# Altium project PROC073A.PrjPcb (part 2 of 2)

## Sheet PROC073A_HD_Connector_60Pin.SchDoc
size 431 x 279 mm; Date: Not shown in title block; ApprovedBy: Not shown in title block; CheckedBy: Not shown in title block; Author: Not shown in title block; CompanyName: Not shown in title block; Engineer: Not shown in title block; Organization: Not shown in title block; Address1: Not shown in title block; Address2: Not shown in title block; Address3: Not shown in title block; Address4: Not shown in title block; DocumentNumber: 1; Revision: Use project parameter SCH_Rev; SheetNumber: 7; SheetTotal: 9; PageSetup: Record=PageOptions¦CenterHorizontal=True¦CenterVertical=True¦PrintScale=1.00¦XCorrection=1.00¦YCorrection=1.00¦PrintKind=0¦BorderSize=5000000¦LeftOffset=0¦BottomOffset=0¦Orientation=2¦PaperLength=1000¦PaperWidth=1000¦Scale=100¦PaperSource=15¦PrintQuality=600¦MediaType=1¦DitherType=10¦PaperKind=Letter¦PrintScaleMode=1
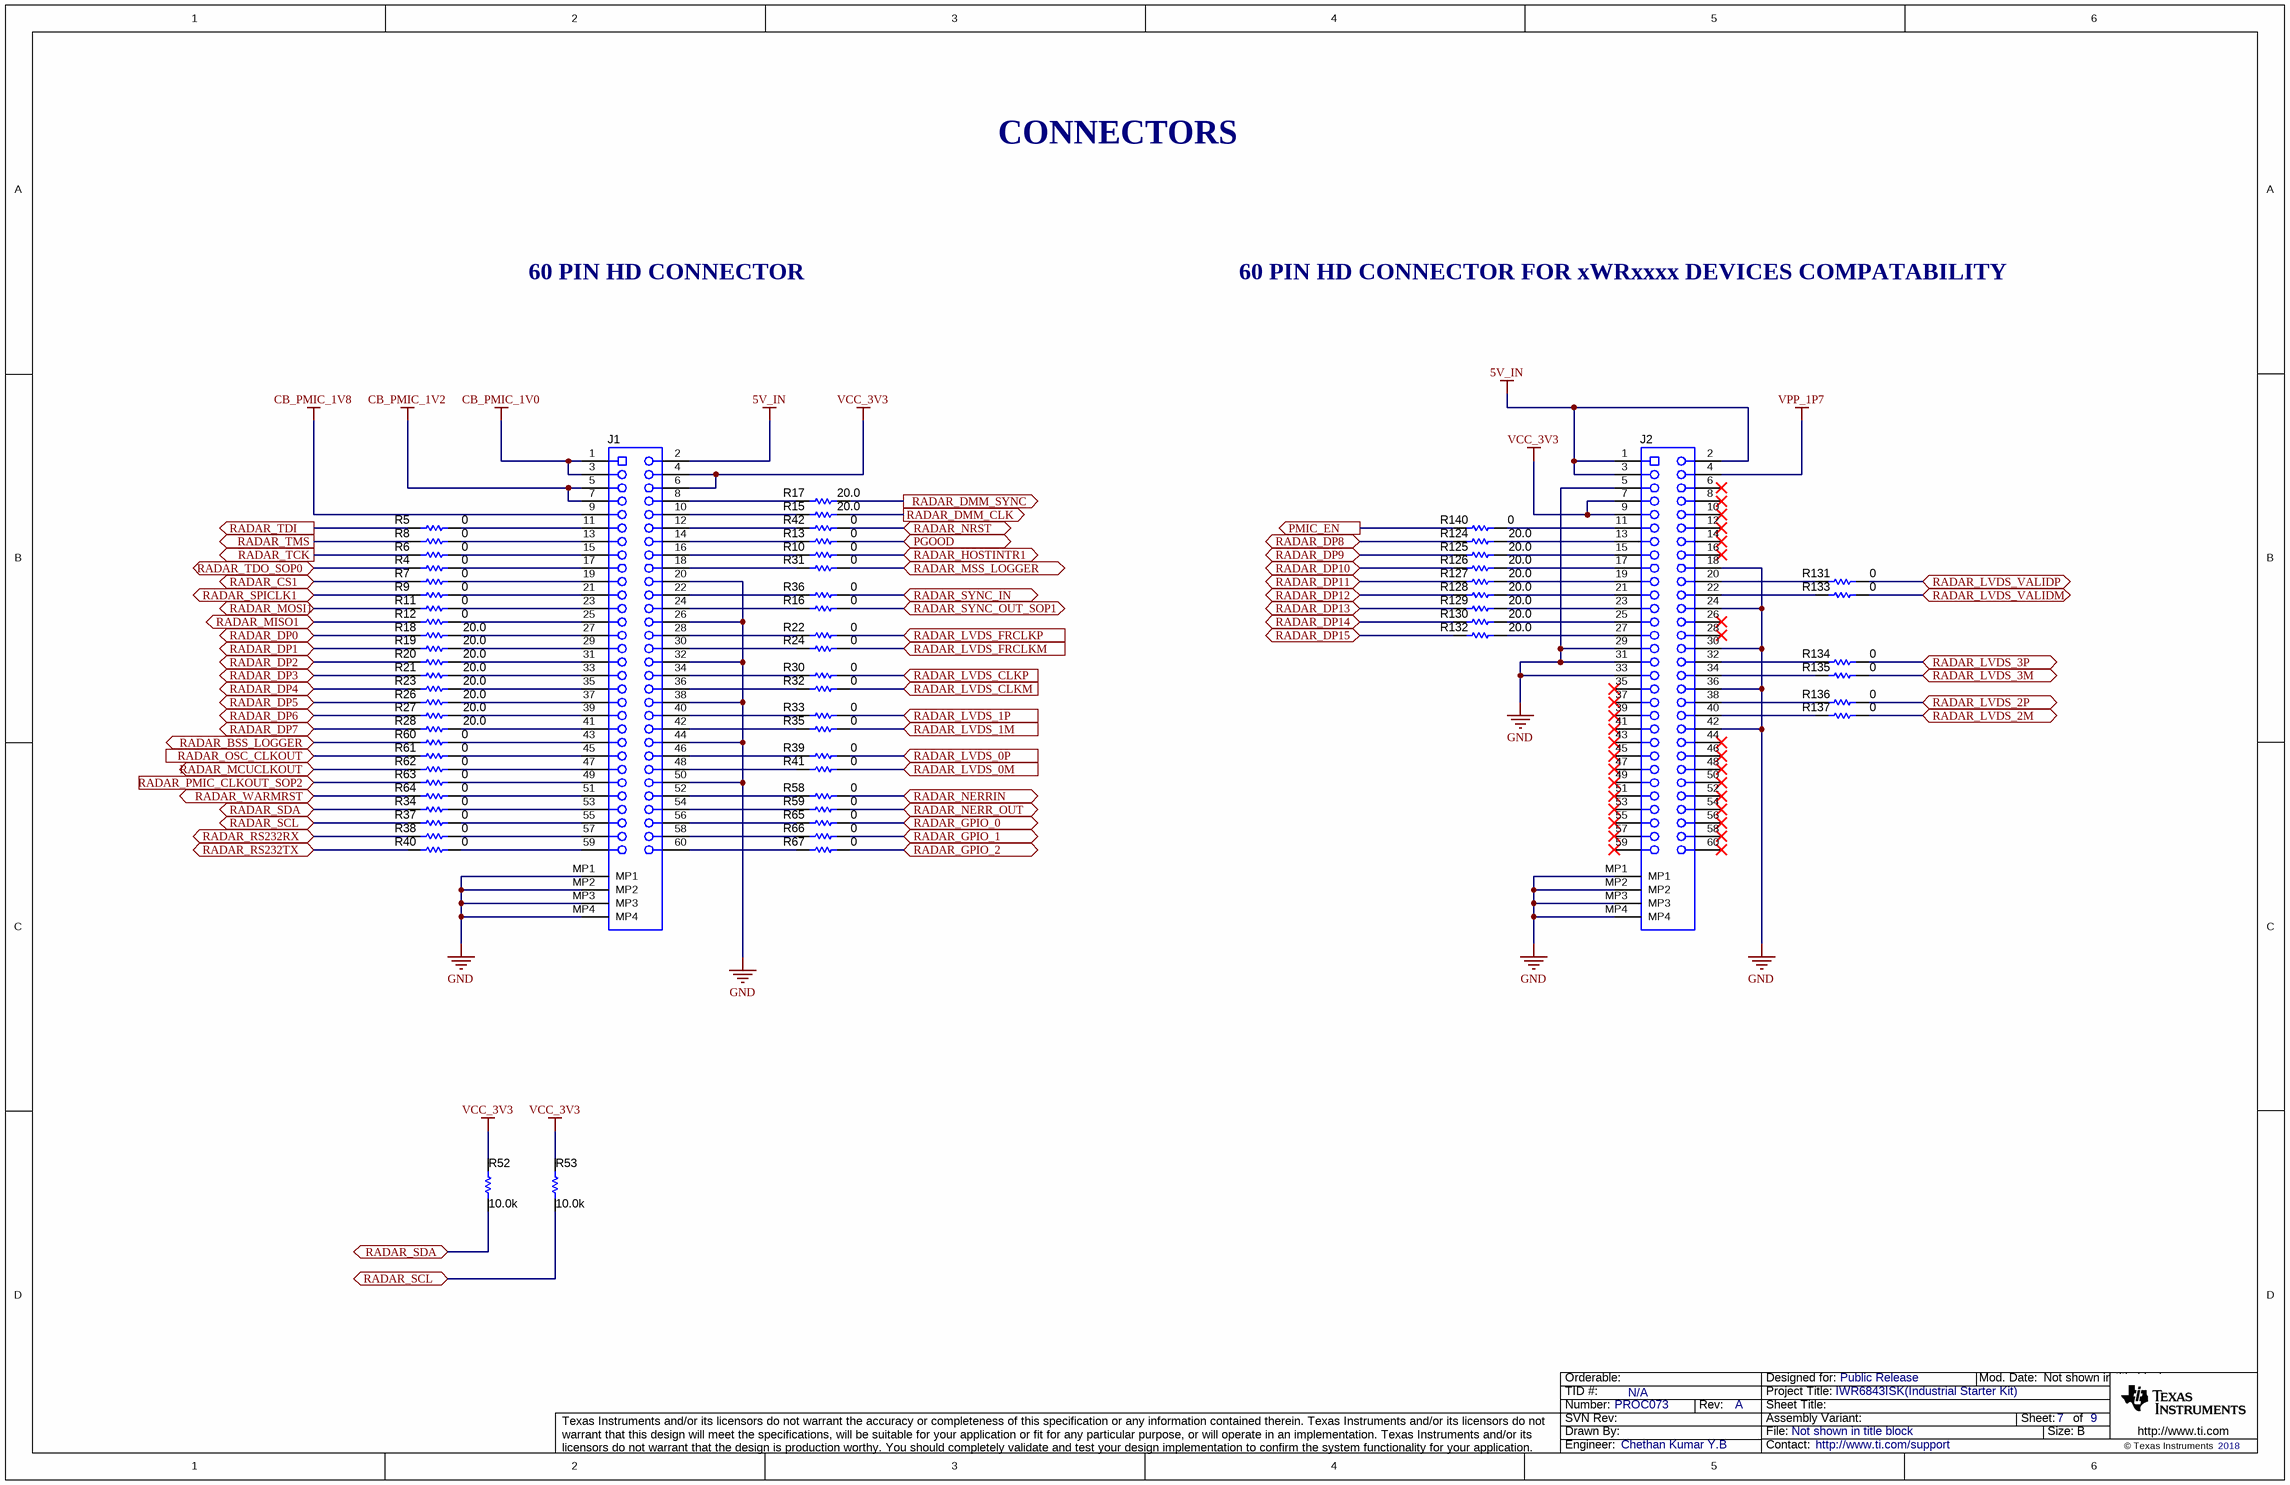
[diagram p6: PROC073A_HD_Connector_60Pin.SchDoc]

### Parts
J1  QSH-030-01-L-D-A  [Samtec_QSH-030-01-X-D-A]  (value not drawn)
J2  QSH-030-01-L-D-A  [Samtec_QSH-030-01-X-D-A]  (value not drawn)
R4  ValueDisplayed: 0  [0201_Silk]  (hidden comment: CRCW02010000Z0ED)
R5  ValueDisplayed: 0  [0201_Silk]  (hidden comment: CRCW02010000Z0ED)
R6  ValueDisplayed: 0  [0201_Silk]  (hidden comment: CRCW02010000Z0ED)
R7  ValueDisplayed: 0  [0201_Silk]  (hidden comment: CRCW02010000Z0ED)
R8  ValueDisplayed: 0  [0201_Silk]  (hidden comment: CRCW02010000Z0ED)
R9  ValueDisplayed: 0  [0201_Silk]  (hidden comment: CRCW02010000Z0ED)
R10  ValueDisplayed: 0  [0201_Silk]  (hidden comment: CRCW02010000Z0ED)
R11  ValueDisplayed: 0  [0201_Silk]  (hidden comment: CRCW02010000Z0ED)
R12  ValueDisplayed: 0  [0201_Silk]  (hidden comment: CRCW02010000Z0ED)
R13  ValueDisplayed: 0  [0201_Silk]  (hidden comment: CRCW02010000Z0ED)
R15  ValueDisplayed: 20.0  [0201_033]  (hidden comment: CRCW020120R0FNED)
R16  ValueDisplayed: 0  [0201_Silk]  (hidden comment: CRCW02010000Z0ED)
R17  ValueDisplayed: 20.0  [0201_033]  (hidden comment: CRCW020120R0FNED)
R18  ValueDisplayed: 20.0  [0201_033]  (hidden comment: CRCW020120R0FNED)
R19  ValueDisplayed: 20.0  [0201_033]  (hidden comment: CRCW020120R0FNED)
R20  ValueDisplayed: 20.0  [0201_033]  (hidden comment: CRCW020120R0FNED)
R21  ValueDisplayed: 20.0  [0201_033]  (hidden comment: CRCW020120R0FNED)
R22  ValueDisplayed: 0  [0201_Silk]  (hidden comment: CRCW02010000Z0ED)
R23  ValueDisplayed: 20.0  [0201_033]  (hidden comment: CRCW020120R0FNED)
R24  ValueDisplayed: 0  [0201_Silk]  (hidden comment: CRCW02010000Z0ED)
R26  ValueDisplayed: 20.0  [0201_033]  (hidden comment: CRCW020120R0FNED)
R27  ValueDisplayed: 20.0  [0201_033]  (hidden comment: CRCW020120R0FNED)
R28  ValueDisplayed: 20.0  [0201_033]  (hidden comment: CRCW020120R0FNED)
R30  ValueDisplayed: 0  [0201_Silk]  (hidden comment: CRCW02010000Z0ED)
R31  ValueDisplayed: 0  [0201_Silk]  (hidden comment: CRCW02010000Z0ED)
R32  ValueDisplayed: 0  [0201_Silk]  (hidden comment: CRCW02010000Z0ED)
R33  ValueDisplayed: 0  [0201_Silk]  (hidden comment: CRCW02010000Z0ED)
R34  ValueDisplayed: 0  [0201_Silk]  (hidden comment: CRCW02010000Z0ED)
R35  ValueDisplayed: 0  [0201_Silk]  (hidden comment: CRCW02010000Z0ED)
R36  ValueDisplayed: 0  [0201_Silk]  (hidden comment: CRCW02010000Z0ED)
R37  ValueDisplayed: 0  [0201_Silk]  (hidden comment: CRCW02010000Z0ED)
R38  ValueDisplayed: 0  [0201_Silk]  (hidden comment: CRCW02010000Z0ED)
R39  ValueDisplayed: 0  [0201_Silk]  (hidden comment: CRCW02010000Z0ED)
R40  ValueDisplayed: 0  [0201_Silk]  (hidden comment: CRCW02010000Z0ED)
R41  ValueDisplayed: 0  [0201_Silk]  (hidden comment: CRCW02010000Z0ED)
R42  ValueDisplayed: 0  [0201_Silk]  (hidden comment: CRCW02010000Z0ED)
R52  ValueDisplayed: 10.0k  [0402L]  (hidden comment: CRCW040210K0FKED)
R53  ValueDisplayed: 10.0k  [0402L]  (hidden comment: CRCW040210K0FKED)
R58  ValueDisplayed: 0  [0201_Silk]  (hidden comment: CRCW02010000Z0ED)
R59  ValueDisplayed: 0  [0201_Silk]  (hidden comment: CRCW02010000Z0ED)
R60  ValueDisplayed: 0  [0201_Silk]  (hidden comment: CRCW02010000Z0ED)
R61  ValueDisplayed: 0  [0201_Silk]  (hidden comment: CRCW02010000Z0ED)
R62  ValueDisplayed: 0  [0201_Silk]  (hidden comment: CRCW02010000Z0ED)
R63  ValueDisplayed: 0  [0201_Silk]  (hidden comment: CRCW02010000Z0ED)
R64  ValueDisplayed: 0  [0201_Silk]  (hidden comment: CRCW02010000Z0ED)
R65  ValueDisplayed: 0  [0201_Silk]  (hidden comment: CRCW02010000Z0ED)
R66  ValueDisplayed: 0  [0201_Silk]  (hidden comment: CRCW02010000Z0ED)
R67  ValueDisplayed: 0  [0201_Silk]  (hidden comment: CRCW02010000Z0ED)
R124  ValueDisplayed: 20.0  [0201_033]  (hidden comment: CRCW020120R0FNED)
R125  ValueDisplayed: 20.0  [0201_033]  (hidden comment: CRCW020120R0FNED)
R126  ValueDisplayed: 20.0  [0201_033]  (hidden comment: CRCW020120R0FNED)
R127  ValueDisplayed: 20.0  [0201_033]  (hidden comment: CRCW020120R0FNED)
R128  ValueDisplayed: 20.0  [0201_033]  (hidden comment: CRCW020120R0FNED)
R129  ValueDisplayed: 20.0  [0201_033]  (hidden comment: CRCW020120R0FNED)
R130  ValueDisplayed: 20.0  [0201_033]  (hidden comment: CRCW020120R0FNED)
R131  ValueDisplayed: 0  [0201_Silk]  (hidden comment: CRCW02010000Z0ED)
R132  ValueDisplayed: 20.0  [0201_033]  (hidden comment: CRCW020120R0FNED)
R133  ValueDisplayed: 0  [0201_Silk]  (hidden comment: CRCW02010000Z0ED)
R134  ValueDisplayed: 0  [0201_Silk]  (hidden comment: CRCW02010000Z0ED)
R135  ValueDisplayed: 0  [0201_Silk]  (hidden comment: CRCW02010000Z0ED)
R136  ValueDisplayed: 0  [0201_Silk]  (hidden comment: CRCW02010000Z0ED)
R137  ValueDisplayed: 0  [0201_Silk]  (hidden comment: CRCW02010000Z0ED)
R140  ValueDisplayed: 0  [0201_Silk]  (hidden comment: CRCW02010000Z0ED)

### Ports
PGOOD, PMIC_EN (out), RADAR_BSS_LOGGER, RADAR_CS1 (bidir), RADAR_DMM_CLK (out), RADAR_DMM_SYNC (out), RADAR_DP0 (bidir), RADAR_DP1 (bidir), RADAR_DP2 (bidir), RADAR_DP3 (bidir), RADAR_DP4 (bidir), RADAR_DP5 (bidir), RADAR_DP6 (bidir), RADAR_DP7 (bidir), RADAR_DP8, RADAR_DP9, RADAR_DP10, RADAR_DP11, RADAR_DP12, RADAR_DP13, RADAR_DP14, RADAR_DP15, RADAR_GPIO_0 (bidir), RADAR_GPIO_1 (bidir), RADAR_GPIO_2 (bidir), RADAR_HOSTINTR1, RADAR_LVDS_0M (in), RADAR_LVDS_0P (in), RADAR_LVDS_1M (in), RADAR_LVDS_1P (in), RADAR_LVDS_2M, RADAR_LVDS_2P, RADAR_LVDS_3M, RADAR_LVDS_3P, RADAR_LVDS_CLKM (in), RADAR_LVDS_CLKP (in), RADAR_LVDS_FRCLKM (in), RADAR_LVDS_FRCLKP (in), RADAR_LVDS_VALIDM, RADAR_LVDS_VALIDP, RADAR_MCUCLKOUT, RADAR_MISO1, RADAR_MOSI1, RADAR_MSS_LOGGER, RADAR_NERR_OUT, RADAR_NERRIN, RADAR_NRST, RADAR_OSC_CLKOUT (in), RADAR_PMIC_CLKOUT_SOP2 (in), RADAR_RS232RX, RADAR_RS232TX, RADAR_SCL, RADAR_SDA, RADAR_SPICLK1 (bidir), RADAR_SYNC_IN, RADAR_SYNC_OUT_SOP1, RADAR_TCK (out), RADAR_TDI (out), RADAR_TDO_SOP0, RADAR_TMS (out), RADAR_WARMRST

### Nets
5V_IN: J1.2 J2.1 J2.2 J2.3
CB_PMIC_1V0: J1.1 J1.3
CB_PMIC_1V2: J1.5 J1.7
CB_PMIC_1V8: J1.9
GND: J1.20 J1.26 J1.32 J1.38 J1.44 J1.50 J1.MP1 J1.MP2 J1.MP3 J1.MP4 J2.5 J2.18 J2.24 J2.29 J2.30 J2.31 J2.33 J2.36 J2.42 J2.MP1 J2.MP2 J2.MP3 J2.MP4
VCC_3V3: J1.4 J1.6 J2.7 J2.9 R52.2 R53.2
VPP_1P7: J2.4
PGOOD: R13.2 ; port PGOOD
PMIC_EN: R140.1 ; port PMIC_EN
RADAR_BSS_LOGGER: R60.2 ; port RADAR_BSS_LOGGER
RADAR_CS1: R7.1 ; port RADAR_CS1
RADAR_DMM_CLK: R15.1 ; port RADAR_DMM_CLK
RADAR_DMM_SYNC: R17.1 ; port RADAR_DMM_SYNC
RADAR_DP0: R18.1 ; port RADAR_DP0
RADAR_DP1: R19.1 ; port RADAR_DP1
RADAR_DP2: R20.1 ; port RADAR_DP2
RADAR_DP3: R21.1 ; port RADAR_DP3
RADAR_DP4: R23.1 ; port RADAR_DP4
RADAR_DP5: R26.1 ; port RADAR_DP5
RADAR_DP6: R27.1 ; port RADAR_DP6
RADAR_DP7: R28.1 ; port RADAR_DP7
RADAR_DP8: R124.1 ; port RADAR_DP8
RADAR_DP9: R125.1 ; port RADAR_DP9
RADAR_DP10: R126.1 ; port RADAR_DP10
RADAR_DP11: R127.1 ; port RADAR_DP11
RADAR_DP12: R128.1 ; port RADAR_DP12
RADAR_DP13: R129.1 ; port RADAR_DP13
RADAR_DP14: R130.1 ; port RADAR_DP14
RADAR_DP15: R132.1 ; port RADAR_DP15
RADAR_GPIO_0: R65.1 ; port RADAR_GPIO_0
RADAR_GPIO_1: R66.2 ; port RADAR_GPIO_1
RADAR_GPIO_2: R67.2 ; port RADAR_GPIO_2
RADAR_HOSTINTR1: R10.2 ; port RADAR_HOSTINTR1
RADAR_LVDS_0M: R41.2 ; port RADAR_LVDS_0M
RADAR_LVDS_0P: R39.2 ; port RADAR_LVDS_0P
RADAR_LVDS_1M: R35.2 ; port RADAR_LVDS_1M
RADAR_LVDS_1P: R33.2 ; port RADAR_LVDS_1P
RADAR_LVDS_2M: R137.2 ; port RADAR_LVDS_2M
RADAR_LVDS_2P: R136.2 ; port RADAR_LVDS_2P
RADAR_LVDS_3M: R135.2 ; port RADAR_LVDS_3M
RADAR_LVDS_3P: R134.2 ; port RADAR_LVDS_3P
RADAR_LVDS_CLKM: R32.2 ; port RADAR_LVDS_CLKM
RADAR_LVDS_CLKP: R30.2 ; port RADAR_LVDS_CLKP
RADAR_LVDS_FRCLKM: R24.2 ; port RADAR_LVDS_FRCLKM
RADAR_LVDS_FRCLKP: R22.2 ; port RADAR_LVDS_FRCLKP
RADAR_LVDS_VALIDM: R133.2 ; port RADAR_LVDS_VALIDM
RADAR_LVDS_VALIDP: R131.2 ; port RADAR_LVDS_VALIDP
RADAR_MCUCLKOUT: R62.2 ; port RADAR_MCUCLKOUT
RADAR_MISO1: R12.2 ; port RADAR_MISO1
RADAR_MOSI1: R11.1 ; port RADAR_MOSI1
RADAR_MSS_LOGGER: R31.2 ; port RADAR_MSS_LOGGER
RADAR_NERR_OUT: R59.2 ; port RADAR_NERR_OUT
RADAR_NERRIN: R58.2 ; port RADAR_NERRIN
RADAR_NRST: R42.1 ; port RADAR_NRST
RADAR_OSC_CLKOUT: R61.2 ; port RADAR_OSC_CLKOUT
RADAR_PMIC_CLKOUT_SOP2: R63.2 ; port RADAR_PMIC_CLKOUT_SOP2
RADAR_RS232RX: R38.1 ; port RADAR_RS232RX
RADAR_RS232TX: R40.1 ; port RADAR_RS232TX
RADAR_SCL: R37.1 R53.1 ; port RADAR_SCL
RADAR_SDA: R34.1 R52.1 ; port RADAR_SDA
RADAR_SPICLK1: R9.1 ; port RADAR_SPICLK1
RADAR_SYNC_IN: R36.2 ; port RADAR_SYNC_IN
RADAR_SYNC_OUT_SOP1: R16.2 ; port RADAR_SYNC_OUT_SOP1
RADAR_TCK: R6.2 ; port RADAR_TCK
RADAR_TDI: R5.1 ; port RADAR_TDI
RADAR_TDO_SOP0: R4.2 ; port RADAR_TDO_SOP0
RADAR_TMS: R8.2 ; port RADAR_TMS
RADAR_WARMRST: R64.2 ; port RADAR_WARMRST
NetJ1_8: J1.8 R17.2
NetJ1_10: J1.10 R15.2
NetJ1_11: J1.11 R5.2
NetJ1_12: J1.12 R42.2
NetJ1_13: J1.13 R8.1
NetJ1_14: J1.14 R13.1
NetJ1_15: J1.15 R6.1
NetJ1_16: J1.16 R10.1
NetJ1_17: J1.17 R4.1
NetJ1_18: J1.18 R31.1
NetJ1_19: J1.19 R7.2
NetJ1_21: J1.21 R9.2
NetJ1_22: J1.22 R36.1
NetJ1_23: J1.23 R11.2
NetJ1_24: J1.24 R16.1
NetJ1_25: J1.25 R12.1
NetJ1_27: J1.27 R18.2
NetJ1_28: J1.28 R22.1
NetJ1_29: J1.29 R19.2
NetJ1_30: J1.30 R24.1
NetJ1_31: J1.31 R20.2
NetJ1_33: J1.33 R21.2
NetJ1_34: J1.34 R30.1
NetJ1_35: J1.35 R23.2
NetJ1_36: J1.36 R32.1
NetJ1_37: J1.37 R26.2
NetJ1_39: J1.39 R27.2
NetJ1_40: J1.40 R33.1
NetJ1_41: J1.41 R28.2
NetJ1_42: J1.42 R35.1
NetJ1_43: J1.43 R60.1
NetJ1_45: J1.45 R61.1
NetJ1_46: J1.46 R39.1
NetJ1_47: J1.47 R62.1
NetJ1_48: J1.48 R41.1
NetJ1_49: J1.49 R63.1
NetJ1_51: J1.51 R64.1
NetJ1_52: J1.52 R58.1
NetJ1_53: J1.53 R34.2
NetJ1_54: J1.54 R59.1
NetJ1_55: J1.55 R37.2
NetJ1_56: J1.56 R65.2
NetJ1_57: J1.57 R38.2
NetJ1_58: J1.58 R66.1
NetJ1_59: J1.59 R40.2
NetJ1_60: J1.60 R67.1
NetJ2_11: J2.11 R140.2
NetJ2_13: J2.13 R124.2
NetJ2_15: J2.15 R125.2
NetJ2_17: J2.17 R126.2
NetJ2_19: J2.19 R127.2
NetJ2_20: J2.20 R131.1
NetJ2_21: J2.21 R128.2
NetJ2_22: J2.22 R133.1
NetJ2_23: J2.23 R129.2
NetJ2_25: J2.25 R130.2
NetJ2_27: J2.27 R132.2
NetJ2_32: J2.32 R134.1
NetJ2_34: J2.34 R135.1
NetJ2_38: J2.38 R136.1
NetJ2_40: J2.40 R137.1

Not connected (* = marked no-connect by the designer): J2 6* 8* 10* 12* 14* 16* 26* 28* 35* 37* 39* 41* 43* 44* 45* 46* 47* 48* 49* 50* 51* 52* 53* 54* 55* 56* 57* 58* 59* 60*

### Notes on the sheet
- CONNECTORS
- 60 PIN HD CONNECTOR
- 60 PIN HD CONNECTOR FOR xWRxxxx DEVICES COMPATABILITY

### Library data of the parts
J1 J2 = CMP-0075524-1: Receptacle, 0.5 mm, 30x2, Gold, TH; Manufacturer: Samtec; Pitch_mm: 0.5; Gender: Female; Green_REACh: Passed; CT: False; Shrouded: N; RowSpacing_mm: 5.73; Green_Lifecycle: Active; Row_Count: 2
R4-R13 R16 R22 R24 R30-R37 R39 R41 R42 R58-R67 R131 R133-R137 R140 = CMP-0027008-3: RES, 0, 5%, 0.05 W, 0201; Manufacturer: Vishay-Dale; Power_W: 50mW; TempCo: ppm/C; Value_Code: 0000; U/M: EA; Value: 0; EIA_Code: E24; SizeX_mm: 0.6; SizeY_mm: 0.3; SizeZ_mm: 0.26; Value2: 0.05W; SizeArea_mm2: 0.18; AEC Qualified: N; AEC Category: Q200
R15 R17-R21 R23 R26-R28 R124-R130 R132 = CMP-0078192-1: RES, 20.0, 1%, 0.05 W, 0201; Manufacturer: Vishay-Dale; Value_Code: 20R0; SizeArea_mm2: 0.18; AEC Qualified: N; AEC Category: Q200; Res_ohm: 20; Value: 20.0; SizeZ_mm: 0.33; EIA_Code: E96; TempCo: 200 ppm/C; Power_W: 50mW; VDC_V: 30V; SizeY_mm: 0.3; Value2: 0.05W; U/M: EA; SizeX_mm: 0.6
R38 R40 = CMP-0027008-3: RES, 0, 5%, 0.05 W, 0201; Manufacturer: Vishay-Dale; Power_W: 50mW; TempCo: ppm/C; Value_Code: 0000; U/M: EA; Value: 0; EIA_Code: E24; SizeX_mm: 0.6; SizeY_mm: 0.3; SizeZ_mm: 0.26; Value2: 0.05W; SizeArea_mm2: 0.18; CompType: Resistor; AEC Qualified: N; AEC Category: Q200; INSTALATION: DNP
R52 R53 = CMP-0025958-2: RES, 10.0 k, 1%, 0.063 W, 0402; Manufacturer: Vishay-Dale; Power_W: 63mW; TempCo: 100 ppm/C; Value_Code: 10k0; U/M: EA; Value: 10.0k; EIA_Code: E96; Res_ohm: 10k; SizeX_mm: 1; SizeY_mm: 0.5; SizeZ_mm: 0.6; Value2: 0.063W; VDC_V: 50V; AEC Category: Q200

## Sheet PROC073A_Temp_Current_sensor.SchDoc
size 431 x 279 mm; Date: Not shown in title block; ApprovedBy: Not shown in title block; CheckedBy: Not shown in title block; Author: Not shown in title block; CompanyName: Not shown in title block; Engineer: Not shown in title block; Organization: Not shown in title block; Address1: Not shown in title block; Address2: Not shown in title block; Address3: Not shown in title block; Address4: Not shown in title block; DocumentNumber: 1; Revision: Use project parameter SCH_Rev; SheetNumber: 8; SheetTotal: 9; PageSetup: Record=PageOptions¦CenterHorizontal=True¦CenterVertical=True¦PrintScale=1.00¦XCorrection=1.00¦YCorrection=1.00¦PrintKind=0¦BorderSize=5000000¦LeftOffset=0¦BottomOffset=0¦Orientation=2¦PaperLength=1000¦PaperWidth=1000¦Scale=100¦PaperSource=15¦PrintQuality=600¦MediaType=1¦DitherType=10¦PaperKind=Letter¦PrintScaleMode=1
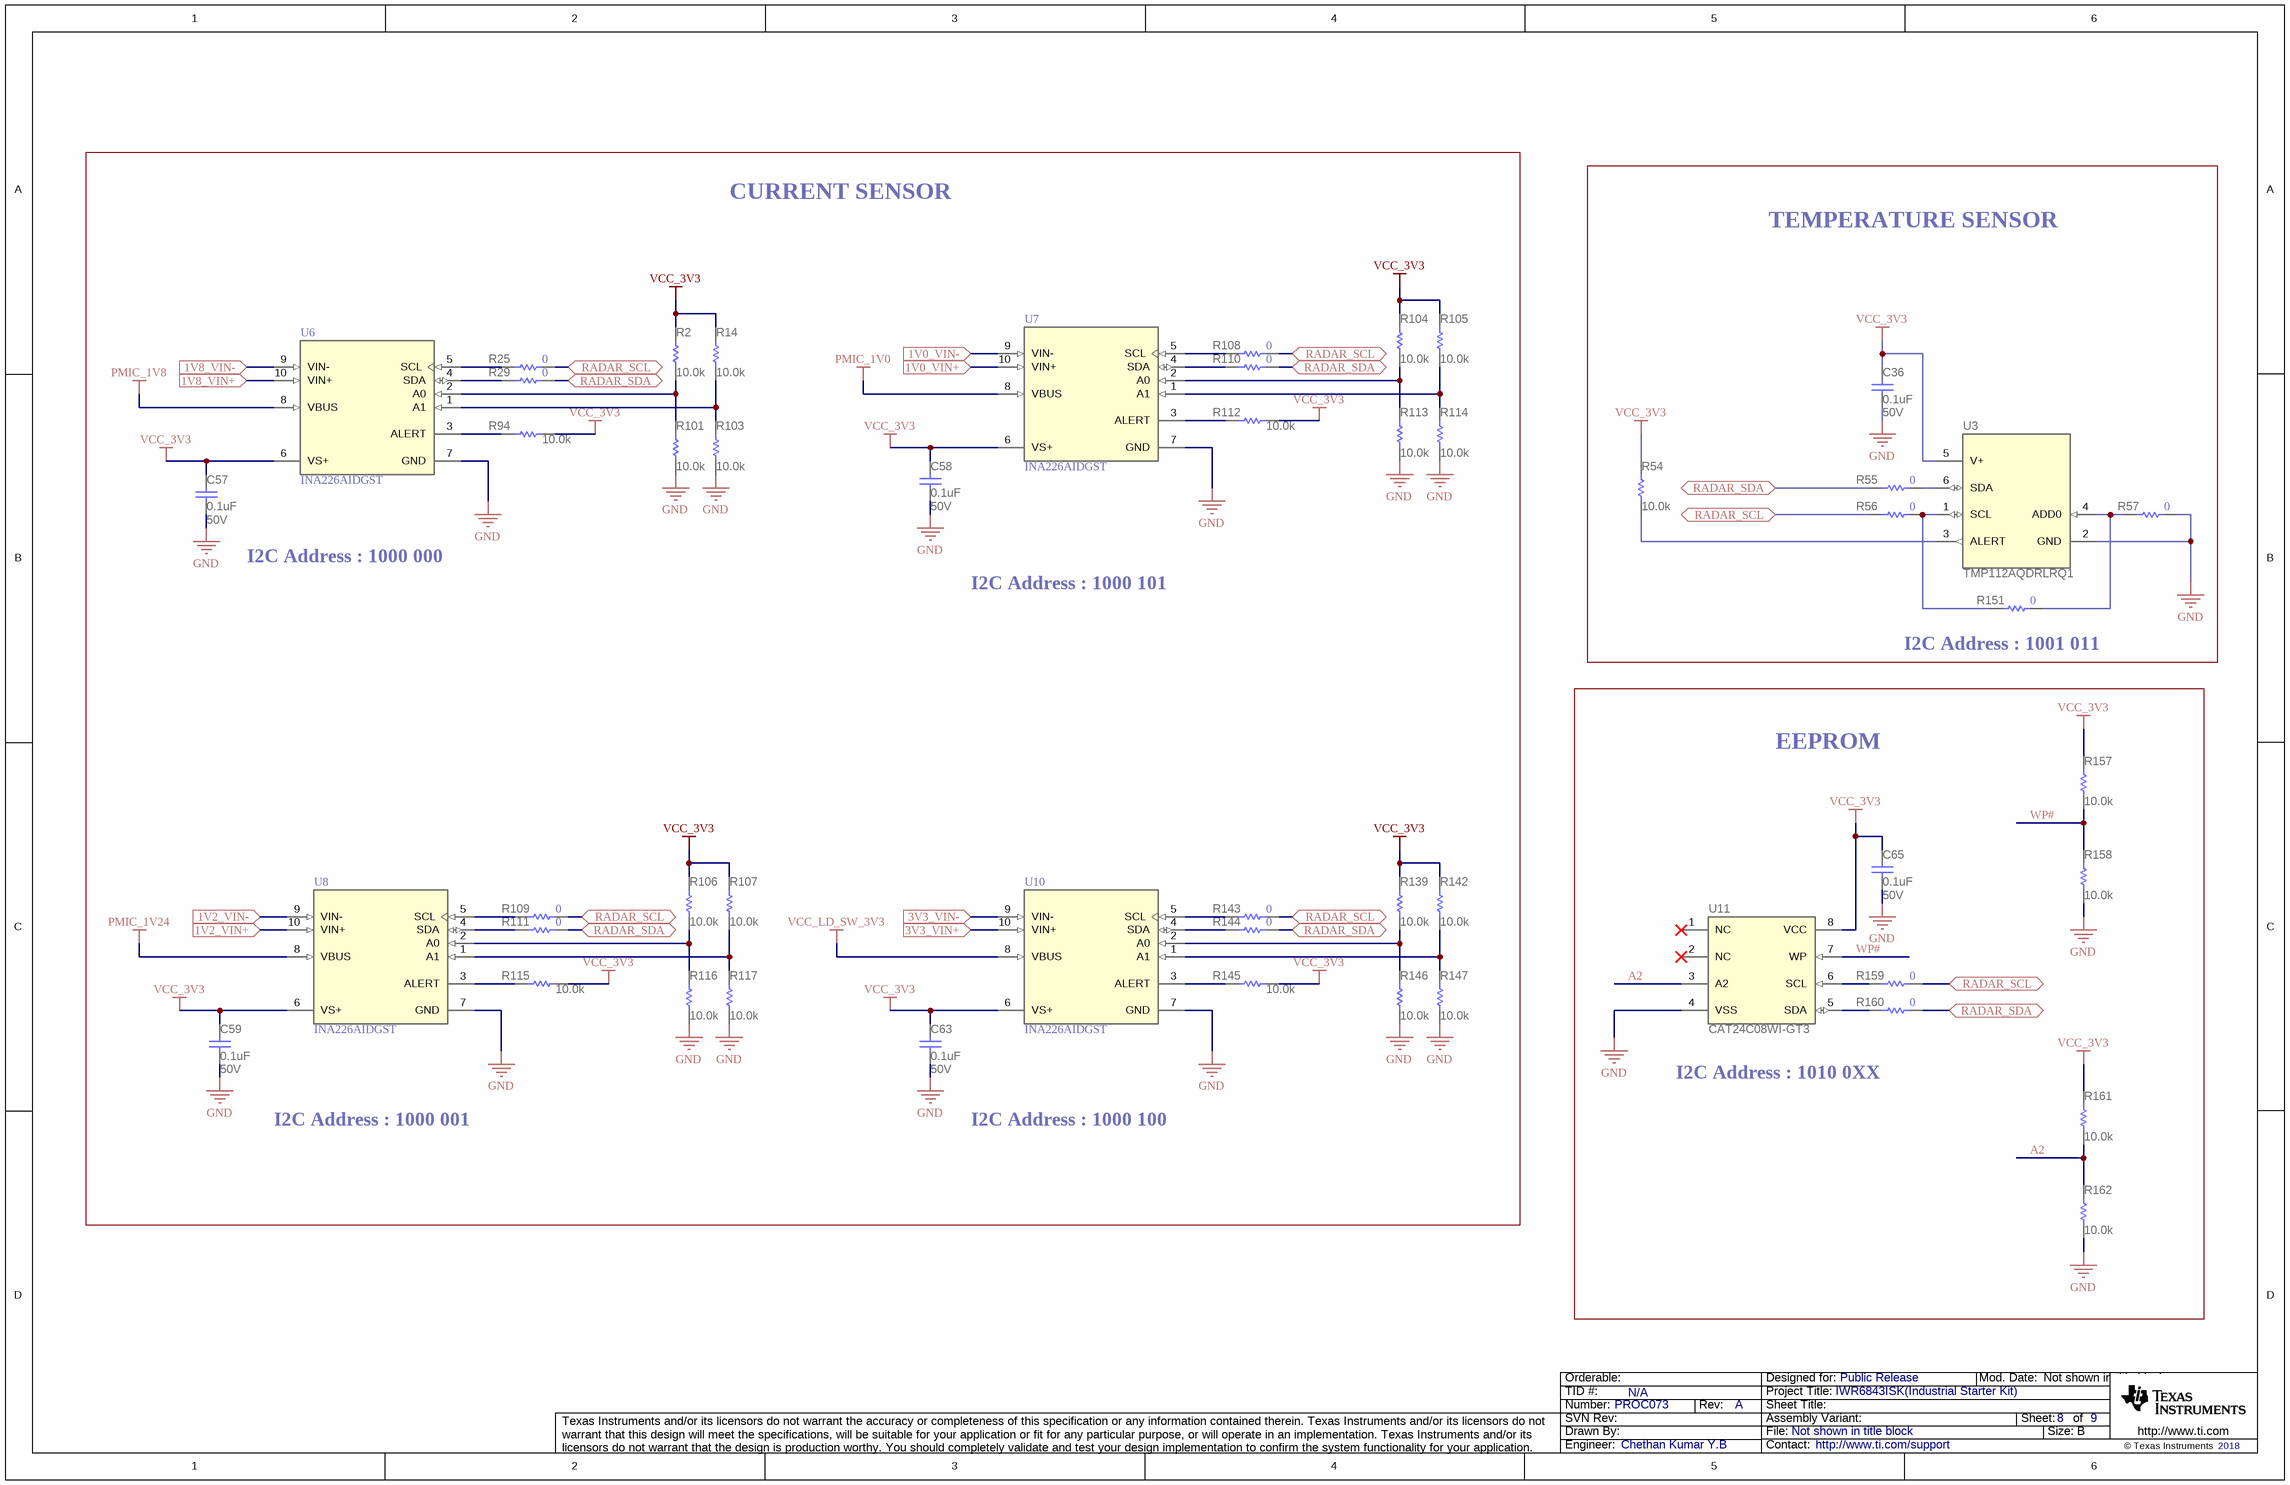
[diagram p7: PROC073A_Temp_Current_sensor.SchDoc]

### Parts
C36  VDC_V: 50V  ValueDisplayed: 0.1uF  [0402L]  (hidden comment: CGA2B3X7R1H104K050BB)
C57  VDC_V: 50V  ValueDisplayed: 0.1uF  [0402L]  (hidden comment: CGA2B3X7R1H104K050BB)
C58  VDC_V: 50V  ValueDisplayed: 0.1uF  [0402L]  (hidden comment: CGA2B3X7R1H104K050BB)
C59  VDC_V: 50V  ValueDisplayed: 0.1uF  [0402L]  (hidden comment: CGA2B3X7R1H104K050BB)
C63  VDC_V: 50V  ValueDisplayed: 0.1uF  [0402L]  (hidden comment: CGA2B3X7R1H104K050BB)
C65  VDC_V: 50V  ValueDisplayed: 0.1uF  [0402L]  (hidden comment: CGA2B3X7R1H104K050BB)
R2  ValueDisplayed: 10.0k  [0402L]  (hidden comment: CRCW040210K0FKED)
R14  ValueDisplayed: 10.0k  [0402L]  (hidden comment: CRCW040210K0FKED)
R25  ValueDisplayed: 0  [0201]  (hidden comment: CRCW02010000Z0ED)
R29  ValueDisplayed: 0  [0201]  (hidden comment: CRCW02010000Z0ED)
R54  ValueDisplayed: 10.0k  [0402L]  (hidden comment: CRCW040210K0FKED)
R55  ValueDisplayed: 0  [0201]  (hidden comment: CRCW02010000Z0ED)
R56  ValueDisplayed: 0  [0201]  (hidden comment: CRCW02010000Z0ED)
R57  Res_ohm: 0  [0402]  (hidden comment: CRCW04020000Z0ED)
R94  ValueDisplayed: 10.0k  [0402L]  (hidden comment: CRCW040210K0FKED)
R101  ValueDisplayed: 10.0k  [0402L]  (hidden comment: CRCW040210K0FKED)
R103  ValueDisplayed: 10.0k  [0402L]  (hidden comment: CRCW040210K0FKED)
R104  ValueDisplayed: 10.0k  [0402L]  (hidden comment: CRCW040210K0FKED)
R105  ValueDisplayed: 10.0k  [0402L]  (hidden comment: CRCW040210K0FKED)
R106  ValueDisplayed: 10.0k  [0402L]  (hidden comment: CRCW040210K0FKED)
R107  ValueDisplayed: 10.0k  [0402L]  (hidden comment: CRCW040210K0FKED)
R108  ValueDisplayed: 0  [0201]  (hidden comment: CRCW02010000Z0ED)
R109  ValueDisplayed: 0  [0201]  (hidden comment: CRCW02010000Z0ED)
R110  ValueDisplayed: 0  [0201]  (hidden comment: CRCW02010000Z0ED)
R111  ValueDisplayed: 0  [0201]  (hidden comment: CRCW02010000Z0ED)
R112  ValueDisplayed: 10.0k  [0402L]  (hidden comment: CRCW040210K0FKED)
R113  ValueDisplayed: 10.0k  [0402L]  (hidden comment: CRCW040210K0FKED)
R114  ValueDisplayed: 10.0k  [0402L]  (hidden comment: CRCW040210K0FKED)
R115  ValueDisplayed: 10.0k  [0402L]  (hidden comment: CRCW040210K0FKED)
R116  ValueDisplayed: 10.0k  [0402L]  (hidden comment: CRCW040210K0FKED)
R117  ValueDisplayed: 10.0k  [0402L]  (hidden comment: CRCW040210K0FKED)
R139  ValueDisplayed: 10.0k  [0402L]  (hidden comment: CRCW040210K0FKED)
R142  ValueDisplayed: 10.0k  [0402L]  (hidden comment: CRCW040210K0FKED)
R143  ValueDisplayed: 0  [0201]  (hidden comment: CRCW02010000Z0ED)
R144  ValueDisplayed: 0  [0201]  (hidden comment: CRCW02010000Z0ED)
R145  ValueDisplayed: 10.0k  [0402L]  (hidden comment: CRCW040210K0FKED)
R146  ValueDisplayed: 10.0k  [0402L]  (hidden comment: CRCW040210K0FKED)
R147  ValueDisplayed: 10.0k  [0402L]  (hidden comment: CRCW040210K0FKED)
R151  Res_ohm: 0  [0402]  (hidden comment: CRCW04020000Z0ED)
R157  ValueDisplayed: 10.0k  [0402L]  (hidden comment: CRCW040210K0FKED)
R158  ValueDisplayed: 10.0k  [0402L]  (hidden comment: CRCW040210K0FKED)
R159  ValueDisplayed: 0  [0201]  (hidden comment: CRCW02010000Z0ED)
R160  ValueDisplayed: 0  [0201]  (hidden comment: CRCW02010000Z0ED)
R161  ValueDisplayed: 10.0k  [0402L]  (hidden comment: CRCW040210K0FKED)
R162  ValueDisplayed: 10.0k  [0402L]  (hidden comment: CRCW040210K0FKED)
U3  TMP112AQDRLRQ1  [DRL0006A]
U6  INA226AIDGST  [DGS0010A_L]
U7  INA226AIDGST  [DGS0010A_L]
U8  INA226AIDGST  [DGS0010A_L]
U10  INA226AIDGST  [DGS0010A_L]
U11  CAT24C08WI-GT3  [SOIC-8]

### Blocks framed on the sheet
CURRENT SENSOR: C57-C59 C63 R2 R14 R25 R29 R94 R101 R103-R117 R139 R142-R147 U6-U8 U10
TEMPERATURE SENSOR: C36 R54-R57 R151 U3
EEPROM: C65 R157-R162 U11

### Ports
1V0_VIN+ (in), 1V0_VIN- (in), 1V2_VIN+ (in), 1V2_VIN- (in), 1V8_VIN+ (in), 1V8_VIN- (in), 3V3_VIN+ (in), 3V3_VIN- (in), RADAR_SCL, RADAR_SDA

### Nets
CB_PMIC_1V0: U7.9(VIN-) ; port 1V0_VIN-
CB_PMIC_1V2: U8.9(VIN-) ; port 1V2_VIN-
CB_PMIC_1V8: U6.9(VIN-) ; port 1V8_VIN-
GND: C36.1 C57.1 C58.1 C59.1 C63.1 C65.1 R57.2 R101.1 R103.1 R113.1 R114.1 R116.1 R117.1 R146.1 R147.1 R158.1 R162.1 U3.2(GND) U6.7(GND) U7.7(GND) U8.7(GND) U10.7(GND) U11.4(VSS)
PMIC_1V0: U7.8(VBUS) U7.10(VIN+) ; port 1V0_VIN+
PMIC_1V8: U6.8(VBUS) U6.10(VIN+) ; port 1V8_VIN+
PMIC_1V24: U8.8(VBUS) U8.10(VIN+) ; port 1V2_VIN+
RADAR_3V3: U10.9(VIN-) ; port 3V3_VIN-
VCC_3V3: C36.2 C57.2 C58.2 C59.2 C63.2 C65.2 R2.2 R14.2 R54.2 R94.1 R104.2 R105.2 R106.2 R107.2 R112.1 R115.1 R139.2 R142.2 R145.1 R157.2 R161.2 U3.5(V+) U6.6(VS+) U7.6(VS+) U8.6(VS+) U10.6(VS+) U11.8(VCC)
VCC_LD_SW_3V3: U10.8(VBUS) U10.10(VIN+) ; port 3V3_VIN+
A2: R161.1 R162.2 U11.3(A2)
RADAR_SCL: R25.2 R56.1 R108.2 R109.2 R143.2 R159.2 ; port RADAR_SCL
RADAR_SDA: R29.2 R55.1 R110.2 R111.2 R144.2 R160.2 ; port RADAR_SDA
WP#: R157.1 R158.2 U11.7(WP)
NetR2_1: R2.1 R101.2 U6.2(A0)
NetR14_1: R14.1 R103.2 U6.1(A1)
NetR25_1: R25.1 U6.5(SCL)
NetR29_1: R29.1 U6.4(SDA)
NetR54_1: R54.1 U3.3(ALERT)
NetR55_2: R55.2 U3.6(SDA)
NetR56_2: R56.2 R151.1 U3.1(SCL)
NetR57_1: R57.1 R151.2 U3.4(ADD0)
NetR94_2: R94.2 U6.3(ALERT)
NetR104_1: R104.1 R113.2 U7.2(A0)
NetR105_1: R105.1 R114.2 U7.1(A1)
NetR106_1: R106.1 R116.2 U8.2(A0)
NetR107_1: R107.1 R117.2 U8.1(A1)
NetR108_1: R108.1 U7.5(SCL)
NetR109_1: R109.1 U8.5(SCL)
NetR110_1: R110.1 U7.4(SDA)
NetR111_1: R111.1 U8.4(SDA)
NetR112_2: R112.2 U7.3(ALERT)
NetR115_2: R115.2 U8.3(ALERT)
NetR139_1: R139.1 R146.2 U10.2(A0)
NetR142_1: R142.1 R147.2 U10.1(A1)
NetR143_1: R143.1 U10.5(SCL)
NetR144_1: R144.1 U10.4(SDA)
NetR145_2: R145.2 U10.3(ALERT)
NetR159_1: R159.1 U11.6(SCL)
NetR160_1: R160.1 U11.5(SDA)

Not connected (* = marked no-connect by the designer): U11 1(NC)* 2(NC)*

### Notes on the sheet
- I2C Address : 1000 000
- I2C Address : 1000 101
- (near R151) I2C Address : 1001 011
- I2C Address : 1010 0XX
- I2C Address : 1000 001
- I2C Address : 1000 100

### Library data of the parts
C36 C57-C59 C63 C65 = CMP-0006325-2: CAP, CERM, 0.1 uF, 50 V, +/- 10%, X7R, AEC-Q200 Grade 1, 0402; Manufacturer: TDK; TaMin_C: -55°C; ESR_ohm: 0.039064; Polarized: N; SizeAreaWB_mm2: 3; Value1: 0.039064 ohm; U/M: EA; Value: 0.1uF; TaMax_C: 125°C; SizeZ_mm: 0.6; SizeX_mm: 1; SizeY_mm: 0.5; Cap_Case: 0402; AEC Qualified: Y; Cap_F: 100nF; IRMS_A: 8.14669dA; AEC Category: Q200
R2 R14 R107 R113 R114 R116 R139 R142 R146 R147 R157 R158 R161 R162 = CMP-0025958-2: RES, 10.0 k, 1%, 0.063 W, 0402; Manufacturer: Vishay-Dale; Power_W: 63mW; TempCo: 100 ppm/C; Value_Code: 10k0; U/M: EA; Value: 10.0k; EIA_Code: E96; Res_ohm: 10k; SizeX_mm: 1; SizeY_mm: 0.5; SizeZ_mm: 0.6; Value2: 0.063W; CompType: Resistor; VDC_V: 50V; AEC Category: Q200; INSTALLATION: DNP
R25 R29 R55 R56 R108-R111 R143 R144 R159 R160 = CMP-0027008-4: RES, 0, 5%, 0.05 W, 0201; Manufacturer: Vishay-Dale; Power_W: 50mW; TempCo: ppm/C; Value_Code: 0000; Value: 0; EIA_Code: E24; SizeX_mm: 0.6; SizeY_mm: 0.3; SizeZ_mm: 0.26; Value2: 0.05W; SizeArea_mm2: 0.18; AEC Qualified: N; AEC Category: Q200
R54 R94 R101 R103-R106 R112 R115 R117 R145 = CMP-0025958-2: as R52 on sheet PROC073A_HD_Connector_60Pin
R57 = CMP-0026822-3: RES, 0, 5%, 0.063 W, AEC-Q200 Grade 0, 0402; Manufacturer: Vishay-Dale; Power_W: 63mW; TempCo: 200 ppm/C; Value_Code: 0000; Value: 0; EIA_Code: E24; SizeX_mm: 1; SizeY_mm: 0.5; SizeZ_mm: 0.6; Value2: 0.063W; CompType: Resistor; AEC Qualified: Y; VDC_V: 50V; AEC Category: Q200; INSTALLATION: DNP
R151 = CMP-0026822-3: RES, 0, 5%, 0.063 W, AEC-Q200 Grade 0, 0402; Manufacturer: Vishay-Dale; Power_W: 63mW; TempCo: 200 ppm/C; Value_Code: 0000; Value: 0; EIA_Code: E24; SizeX_mm: 1; SizeY_mm: 0.5; SizeZ_mm: 0.6; Value2: 0.063W; CompType: Resistor; AEC Qualified: Y; VDC_V: 50V; AEC Category: Q200
U3 = CMP-0067398-2: Automotive Grade, 1.4V-Capable +/-0.5degC Temperature Sensor with Alert Function and I2C/SMBus, DRL0006A (SOT-OTHER-6); Manufacturer: Texas Instruments; SizeZ_mm: 0.6; SizeX_mm: 1.6; SizeArea_mm2: 2.56; CompType: IC; U/M: EA; SizeAreaWB_mm2: 6.76
U6-U8 U10 = CMP-0037978-1: High-Side Measurement, Bi-Directional Current / Power Monitor with I2C Interface, 2.7 to 5.5 V, -40 to 125 degC, 10-pin SOP (DGS10), Green (RoHS & no Sb/Br); Vs(Min)(V): 2.7; Rating: Catalog; Quiescent Current (+/-)(Typ)(mA): 0.33; Input Offset (+/-)(Max)(uV): 10; CMRR(Min)(dB): 126; Vs(Max)(V): 5.5; Common Mode Range(Max)(V): 36; Input Offset Drift (+/-)(Max)(uV/Degrees Celsius): 0.1; Common Mode Range(Min)(V): 0; SubFamily: Current Shunt Monitor; Gain(V/V): 1; Small-Signal Bandwidth(Typ)(MHz): 0.007
U11 = CMP-0005309-2: IC, EEPROM, 8KBIT, 400KHZ, 8SOIC; Manufacturer: ON Semiconductor; SizeAreaWB_mm2: 55.131; SizeZ_mm: 1.75; SizeX_mm: 5.99; SizeY_mm: 4.9; SizeArea_mm2: 29.351

## Sheet PROC073A_EVM_Hardware.SchDoc
size 431 x 279 mm; Date: Not shown in title block; ApprovedBy: Not shown in title block; CheckedBy: Not shown in title block; Author: Not shown in title block; CompanyName: Not shown in title block; Engineer: Not shown in title block; Organization: Not shown in title block; Address1: Not shown in title block; Address2: Not shown in title block; Address3: Not shown in title block; Address4: Not shown in title block; DocumentNumber: 1; Revision: Use project parameter SCH_Rev; SheetNumber: 9; SheetTotal: 9; PageSetup: Record=PageOptions¦CenterHorizontal=True¦CenterVertical=True¦PrintScale=1.00¦XCorrection=1.00¦YCorrection=1.00¦PrintKind=0¦BorderSize=5000000¦LeftOffset=0¦BottomOffset=0¦Orientation=2¦PaperLength=1000¦PaperWidth=1000¦Scale=100¦PaperSource=15¦PrintQuality=600¦MediaType=1¦DitherType=10¦PaperKind=Letter¦PrintScaleMode=1
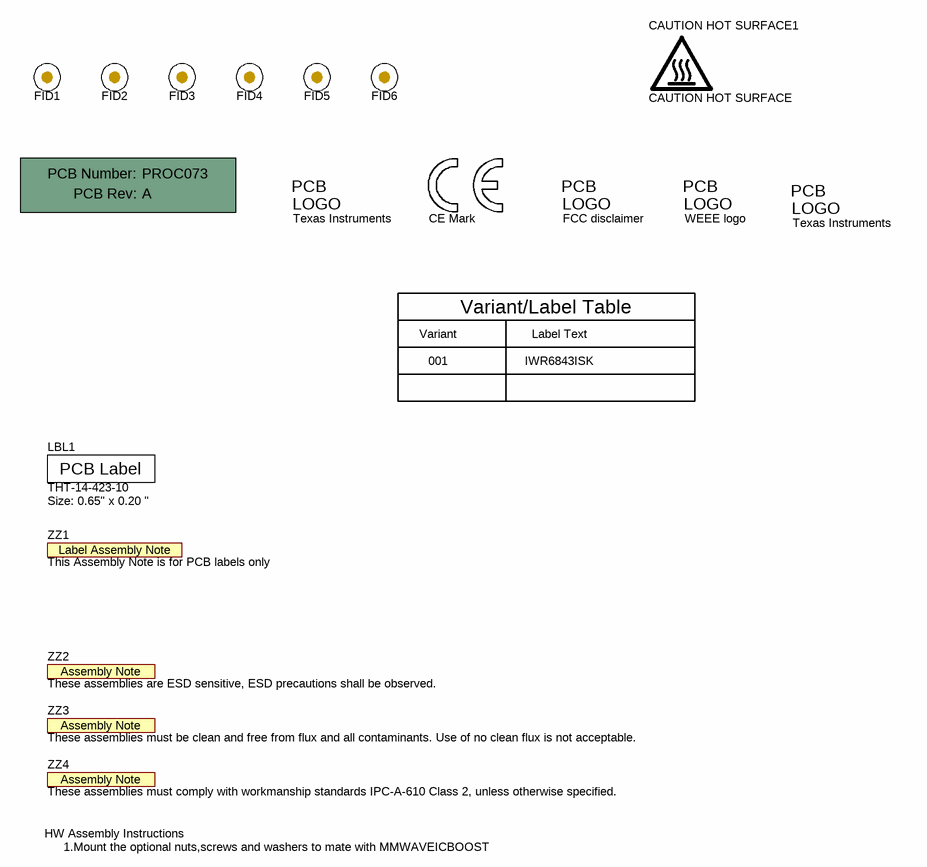
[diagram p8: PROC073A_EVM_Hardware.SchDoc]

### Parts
!PCB  Printed Circuit Board  (value not drawn)  (mechanical)
CAUTION_HOT_SURFACE1  CAUTION HOT SURFACE  [IEC_HotSurface_Small]  (no BOM)
FID1  Fiducial  [Fiducial10-20]  (value not drawn)
FID2  Fiducial  [Fiducial10-20]  (value not drawn)
FID3  Fiducial  [Fiducial10-20]  (value not drawn)
FID4  Fiducial  [Fiducial10-20]  (value not drawn)
FID5  Fiducial  [Fiducial10-20]  (value not drawn)
FID6  Fiducial  [Fiducial10-20]  (value not drawn)
LBL1  THT-14-423-10  Note: Size: 0.65" x 0.20 "  [Label_650x200]
Logo1  Texas Instruments  [TI_Stacked_Overlay_Small]  (no BOM)
Logo2  CE Mark  [CE_Mark_5mm]  (no BOM)
Logo3  FCC disclaimer  [FCC_disclaimer]  (no BOM)
Logo4  WEEE logo  [WEEE_Minimum]  (no BOM)
Logo5  Texas Instruments  [TI_Symbol_Overlay_Small]  (no BOM)
ZZ1  This Assembly Note is for PCB labels only  [AssemblyNoteLabel]  (no BOM)
ZZ2  These assemblies are ESD sensitive, ESD precautions shall be observed.  [AssemblyNote]  (no BOM)
ZZ3  These assemblies must be clean and free from flux and all contaminants. Use of no clean flux is not acceptable.  [AssemblyNote]  (no BOM)
ZZ4  These assemblies must comply with workmanship standards IPC-A-610 Class 2, unless otherwise specified.  [AssemblyNote]  (no BOM)

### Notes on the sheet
- Variant
- 001
- Variant/Label Table
- Label Text
- IWR6843ISK
- (near ZZ4) HW Assembly Instructions
- 1.Mount the optional nuts,screws and washers to mate with MMWAVEICBOOST

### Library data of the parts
!PCB = CMP-0003618-2: Manufacturer: Any; PartNumber: PROC073
CAUTION_HOT_SURFACE1 = CMP-0074837-1: IEC 61010-1 Hot Surface Warning; Library Reference: IEC_HotSurface; SymbolCreator: a0412235
FID1-FID6 = CMP-0077181-1: Fiducial mark.  There is nothing to buy or mount.
LBL1 = CMP-0003625-1: Thermal Transfer Printable Labels, 0.650" W x 0.200" H - 10,000 per roll; Manufacturer: Brady; CompType: Label
Logo1 = CMP-0074838-1: Texas Instrument Corporate Signature; SymbolCreator: a0412235; Lib Reference: TI_Logo; Library Reference: Logo
Logo2 = CMP-0074844-1: SymbolCreator: a0412235
Logo3 = CMP-0074847-1: FCC_disclaimer; Library Reference: Logo
Logo4 = CMP-0074769-1
Logo5 = CMP-0074838-1: Texas Instrument Corporate Signature; Library Reference: Logo; SymbolCreator: a0412235; Lib Reference: TI_Logo
ZZ1 = CMP-0003616-3
ZZ2 = CMP-0077236-1
ZZ3 = CMP-0077237-1
ZZ4 = CMP-0077238-1

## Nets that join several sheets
CB_PMIC_1V0: PROC073A_PMIC (R71.2), PROC073A_Decoupling_caps (C2.2 C3.2 L2.1 L3.1), PROC073A_HD_Connector_60Pin (J1.1 J1.3), PROC073A_Temp_Current_sensor (U7.9)
CB_PMIC_1V2: PROC073A_PMIC (R96.2), PROC073A_Decoupling_caps (C64.2 L7.1), PROC073A_HD_Connector_60Pin (J1.5 J1.7), PROC073A_Temp_Current_sensor (U8.9)
CB_PMIC_1V8: PROC073A_PMIC (R70.2 R99.1), PROC073A_Decoupling_caps (C1.2 L1.1), PROC073A_HD_Connector_60Pin (J1.9), PROC073A_Temp_Current_sensor (U6.9)
GND: PROC073A_PMIC (48 pins), PROC073A_IWR6843_Chip (77 pins), PROC073A_Decoupling_caps (31 pins), PROC073A_QSPI_Flash_section (C34.1 C35.1 U2.4 U2.9), PROC073A_HD_Connector_60Pin (23 pins), PROC073A_Temp_Current_sensor (23 pins)
PMIC_1V0: PROC073A_PMIC (R3.2 R68.2 R71.1), PROC073A_Temp_Current_sensor (U7.8 U7.10)
PMIC_1V8: PROC073A_PMIC (5 pins), PROC073A_Temp_Current_sensor (U6.8 U6.10)
PMIC_1V24: PROC073A_PMIC (6 pins), PROC073A_Temp_Current_sensor (U8.8 U8.10)
RADAR_1P0_RF1: PROC073A_IWR6843_Chip (U1.G5 U1.H5 U1.J5), PROC073A_Decoupling_caps (C19.2 C23.2 L3.2)
RADAR_1P0_RF2: PROC073A_IWR6843_Chip (U1.C2 U1.D2), PROC073A_Decoupling_caps (C20.2 C24.2 L2.2 R1.1)
RADAR_1V2: PROC073A_PMIC (R86.2), PROC073A_IWR6843_Chip (6 pins), PROC073A_Decoupling_caps (7 pins)
RADAR_1V4_APLL: PROC073A_IWR6843_Chip (U1.A10), PROC073A_Decoupling_caps (C22.2)
RADAR_1V4_SYNTH: PROC073A_IWR6843_Chip (U1.B13), PROC073A_Decoupling_caps (C18.2)
RADAR_1V8: PROC073A_PMIC (R166.1), PROC073A_IWR6843_Chip (6 pins), PROC073A_Decoupling_caps (9 pins)
RADAR_3V3: PROC073A_PMIC (R123.2 R170.2), PROC073A_IWR6843_Chip (7 pins), PROC073A_Decoupling_caps (C16.2 C17.2 C21.2), PROC073A_Temp_Current_sensor (U10.9)
RADAR_VBGAP: PROC073A_IWR6843_Chip (U1.B10), PROC073A_Decoupling_caps (C6.2)
RADAR_VOUT_PA: PROC073A_IWR6843_Chip (U1.A2 U1.B2), PROC073A_Decoupling_caps (C4.2 C7.2 C8.2 R1.2)
VCC_3V3: PROC073A_PMIC (26 pins), PROC073A_QSPI_Flash_section (R43.2 R44.2 R49.2 R50.1), PROC073A_HD_Connector_60Pin (6 pins), PROC073A_Temp_Current_sensor (27 pins)
VCC_LD_SW_3V3: PROC073A_PMIC (5 pins), PROC073A_Temp_Current_sensor (U10.8 U10.10)
VPP_1P7: PROC073A_IWR6843_Chip (C31.2 U1.L13), PROC073A_HD_Connector_60Pin (J2.4)
MON_1V: PROC073A_PMIC (7 pins), PROC073A_IWR6843_Chip (R72.1 TP2.1)
PGOOD: PROC073A_PMIC (R79.1 R80.2 R148.1 R149.2), PROC073A_HD_Connector_60Pin (R13.2)
PMIC_EN: PROC073A_PMIC (R118.1 U4.11 U4.19), PROC073A_HD_Connector_60Pin (R140.1)
RADAR_BSS_LOGGER: PROC073A_IWR6843_Chip (U1.H14), PROC073A_HD_Connector_60Pin (R60.2)
RADAR_CS1: PROC073A_IWR6843_Chip (R156.1 U1.E15), PROC073A_HD_Connector_60Pin (R7.1)
RADAR_DMM_CLK: PROC073A_IWR6843_Chip (U1.N15), PROC073A_HD_Connector_60Pin (R15.1)
RADAR_DMM_SYNC: PROC073A_IWR6843_Chip (U1.N14), PROC073A_HD_Connector_60Pin (R17.1)
RADAR_DP0: PROC073A_IWR6843_Chip (U1.R4), PROC073A_HD_Connector_60Pin (R18.1)
RADAR_DP1: PROC073A_IWR6843_Chip (U1.P5), PROC073A_HD_Connector_60Pin (R19.1)
RADAR_DP2: PROC073A_IWR6843_Chip (U1.R5), PROC073A_HD_Connector_60Pin (R20.1)
RADAR_DP3: PROC073A_IWR6843_Chip (U1.P6), PROC073A_HD_Connector_60Pin (R21.1)
RADAR_DP4: PROC073A_IWR6843_Chip (U1.R7), PROC073A_HD_Connector_60Pin (R23.1)
RADAR_DP5: PROC073A_IWR6843_Chip (U1.P7), PROC073A_HD_Connector_60Pin (R26.1)
RADAR_DP6: PROC073A_IWR6843_Chip (U1.R8), PROC073A_HD_Connector_60Pin (R27.1)
RADAR_DP7: PROC073A_IWR6843_Chip (U1.P8), PROC073A_HD_Connector_60Pin (R28.1)
RADAR_GPIO_0: PROC073A_IWR6843_Chip (U1.H13), PROC073A_HD_Connector_60Pin (R65.1)
RADAR_GPIO_1: PROC073A_IWR6843_Chip (U1.J13), PROC073A_HD_Connector_60Pin (R66.2)
RADAR_GPIO_2: PROC073A_PMIC (R171.2), PROC073A_IWR6843_Chip (U1.K13), PROC073A_HD_Connector_60Pin (R67.2)
RADAR_HOSTINTR1: PROC073A_IWR6843_Chip (R152.2 U1.P13), PROC073A_HD_Connector_60Pin (R10.2)
RADAR_LVDS_0M: PROC073A_IWR6843_Chip (U1.J15), PROC073A_HD_Connector_60Pin (R41.2)
RADAR_LVDS_0P: PROC073A_IWR6843_Chip (U1.J14), PROC073A_HD_Connector_60Pin (R39.2)
RADAR_LVDS_1M: PROC073A_IWR6843_Chip (U1.K15), PROC073A_HD_Connector_60Pin (R35.2)
RADAR_LVDS_1P: PROC073A_IWR6843_Chip (U1.K14), PROC073A_HD_Connector_60Pin (R33.2)
RADAR_LVDS_CLKM: PROC073A_IWR6843_Chip (U1.L15), PROC073A_HD_Connector_60Pin (R32.2)
RADAR_LVDS_CLKP: PROC073A_IWR6843_Chip (U1.L14), PROC073A_HD_Connector_60Pin (R30.2)
RADAR_LVDS_FRCLKM: PROC073A_IWR6843_Chip (U1.M15), PROC073A_HD_Connector_60Pin (R24.2)
RADAR_LVDS_FRCLKP: PROC073A_IWR6843_Chip (U1.M14), PROC073A_HD_Connector_60Pin (R22.2)
RADAR_MCUCLKOUT: PROC073A_PMIC (R121.1), PROC073A_IWR6843_Chip (U1.N8), PROC073A_HD_Connector_60Pin (R62.2)
RADAR_MISO1: PROC073A_IWR6843_Chip (U1.E14), PROC073A_HD_Connector_60Pin (R12.2)
RADAR_MOSI1: PROC073A_IWR6843_Chip (U1.D13), PROC073A_HD_Connector_60Pin (R11.1)
RADAR_MSS_LOGGER: PROC073A_IWR6843_Chip (U1.F14), PROC073A_HD_Connector_60Pin (R31.2)
RADAR_NERR_OUT: PROC073A_PMIC (R93.1), PROC073A_IWR6843_Chip (R169.1 U1.N6), PROC073A_HD_Connector_60Pin (R59.2)
RADAR_NERRIN: PROC073A_IWR6843_Chip (R150.1 U1.N7), PROC073A_HD_Connector_60Pin (R58.2)
RADAR_NRST: PROC073A_PMIC (5 pins), PROC073A_IWR6843_Chip (U1.R3), PROC073A_HD_Connector_60Pin (R42.1)
RADAR_OSC_CLKOUT: PROC073A_IWR6843_Chip (U1.A14), PROC073A_HD_Connector_60Pin (R61.2)
RADAR_PMIC_CLKOUT_SOP2: PROC073A_PMIC (R102.1 R165.1), PROC073A_IWR6843_Chip (U1.P9), PROC073A_HD_Connector_60Pin (R63.2)
RADAR_QSPI_CS: PROC073A_IWR6843_Chip (U1.P11), PROC073A_QSPI_Flash_section (R50.2 U2.1)
RADAR_QSPI_D0: PROC073A_IWR6843_Chip (U1.R13), PROC073A_QSPI_Flash_section (R45.2)
RADAR_QSPI_D1: PROC073A_IWR6843_Chip (U1.N12), PROC073A_QSPI_Flash_section (R46.1)
RADAR_QSPI_D2: PROC073A_IWR6843_Chip (U1.R14), PROC073A_QSPI_Flash_section (R44.1 R47.1)
RADAR_QSPI_D3: PROC073A_IWR6843_Chip (U1.P12), PROC073A_QSPI_Flash_section (R49.1 R51.2)
RADAR_QSPI_SCLK: PROC073A_IWR6843_Chip (U1.R12), PROC073A_QSPI_Flash_section (R48.2)
RADAR_RS232RX: PROC073A_IWR6843_Chip (R154.1 U1.N4), PROC073A_HD_Connector_60Pin (R38.1)
RADAR_RS232TX: PROC073A_IWR6843_Chip (R153.1 U1.N5), PROC073A_HD_Connector_60Pin (R40.1)
RADAR_SCL: PROC073A_PMIC (R89.1), PROC073A_IWR6843_Chip (U1.G14), PROC073A_HD_Connector_60Pin (R37.1 R53.1), PROC073A_Temp_Current_sensor (6 pins)
RADAR_SDA: PROC073A_PMIC (R88.1), PROC073A_IWR6843_Chip (U1.F13), PROC073A_HD_Connector_60Pin (R34.1 R52.1), PROC073A_Temp_Current_sensor (6 pins)
RADAR_SPICLK1: PROC073A_IWR6843_Chip (U1.E13), PROC073A_HD_Connector_60Pin (R9.1)
RADAR_SYNC_IN: PROC073A_IWR6843_Chip (R155.2 U1.P4), PROC073A_HD_Connector_60Pin (R36.2)
RADAR_SYNC_OUT_SOP1: PROC073A_IWR6843_Chip (U1.G13), PROC073A_HD_Connector_60Pin (R16.2)
RADAR_TCK: PROC073A_IWR6843_Chip (U1.P10), PROC073A_HD_Connector_60Pin (R6.2)
RADAR_TDI: PROC073A_IWR6843_Chip (U1.R11), PROC073A_HD_Connector_60Pin (R5.1)
RADAR_TDO_SOP0: PROC073A_IWR6843_Chip (U1.N13), PROC073A_HD_Connector_60Pin (R4.2)
RADAR_TMS: PROC073A_IWR6843_Chip (U1.N10), PROC073A_HD_Connector_60Pin (R8.2)
RADAR_WARMRST: PROC073A_PMIC (R98.1), PROC073A_IWR6843_Chip (U1.N9), PROC073A_HD_Connector_60Pin (R64.2)

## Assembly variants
001: not fitted C1 C2 C3 C8 C52 C53 C64 FID1 FID2 FID3 FID4 FID5 FID6 R2 R3 R14 R57 R69 R90 R91 R93 R95 R98 R100 R102 R107 R113 R114 R116 R122 R138 R139 R147 R157 R161 R164 R165 R168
